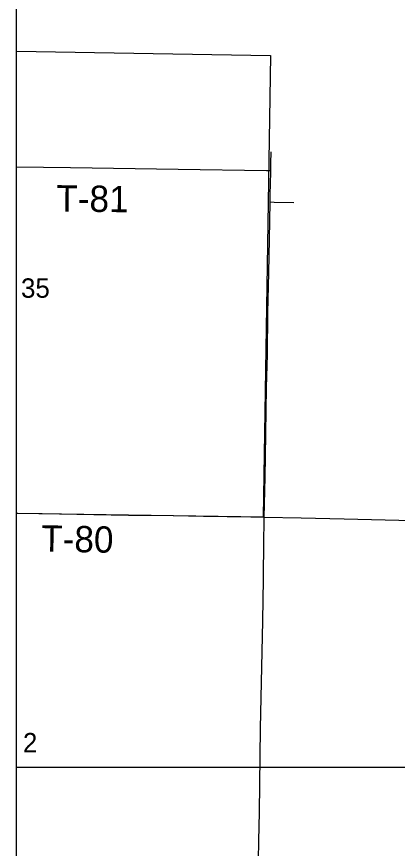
# Model space of a CAD drawing. Extents: x 0 to 68, y 0 to 52.9.
# Drawn here: x 49.517 to 51.689, y 42.989 to 47.729 of the extents above; entities that cross this region are included whole.
import ezdxf

# ---------------------------------------------------------------- set-up
doc = ezdxf.new("R2010")
doc.units = 0
for name, color, linetype in [('Default', 7, 'Continuous'), ('GM_X_Township_Road', 7, 'Continuous'), ('GM_X_Township_Road_Text', 7, 'Continuous')]:
    doc.layers.add(name, color=color, linetype=linetype)

msp = doc.modelspace()

# ---------------------------------------------------------------- linework, layer by layer
at = {"layer": 'Default'}
for p, q in [((49.5172, 34.4614), (49.5172, 52.9414)), ((49.5172, 43.4514), (67.9972, 43.4514))]:
    msp.add_line(p, q, dxfattribs=at)
msp.add_lwpolyline([(49.5172, 47.5317), (50.965, 47.5066), (50.9246, 44.8761), (49.5172, 44.8972)], dxfattribs=at)
at = {"layer": 'GM_X_Township_Road'}
for points in [[(50.9676, 46.8517), (50.9679, 46.8919), (50.9692, 46.959)], [(49.5172, 46.8723), (49.8238, 46.8682), (50.4384, 46.8586), (50.9432, 46.8521), (50.9676, 46.8517)], [(50.963, 46.6725), (50.9637, 46.7138), (50.9676, 46.8429), (50.9676, 46.8517)], [(50.9298, 44.8767), (50.9316, 44.9512), (50.9346, 45.1069), (50.9365, 45.2217), (50.9413, 45.4841), (50.943, 45.6153), (50.9478, 45.8036), (50.9511, 46.0415), (50.9553, 46.271), (50.9594, 46.4596), (50.963, 46.6725)], [(50.963, 46.6725), (50.9863, 46.672), (51.0979, 46.6695)], [(49.5172, 44.8991), (49.5245, 44.899), (49.6638, 44.8963), (50.156, 44.8878), (50.4103, 44.8855), (50.5824, 44.882), (50.8532, 44.8783), (50.9298, 44.8767)], [(50.887, 42.337), (50.8906, 42.5401), (50.8957, 42.8107), (50.8992, 43.0321), (50.9026, 43.196), (50.9087, 43.6712), (50.9212, 44.2861), (50.9251, 44.5239), (50.9275, 44.7453), (50.9293, 44.8435), (50.9298, 44.8767)], [(50.9298, 44.8767), (51.1402, 44.8725), (51.3862, 44.8673), (51.6978, 44.8598), (52.1325, 44.8509), (52.2551, 44.8479)]]:
    msp.add_lwpolyline(points, dxfattribs=at)

# ---------------------------------------------------------------- texts
at = {"layer": 'Default'}
for s, p in [('35', (49.5422, 46.1267)), ('2', (49.5532, 43.536))]:
    msp.add_text(s, height=0.1105, rotation=0, dxfattribs=at).set_placement(p)
at = {"layer": 'GM_X_Township_Road_Text'}
for s, rotation, p in [('T-81', 359.2931, (49.7428, 46.6187)), ('T-80', 358.9386, (49.6562, 44.6806))]:
    msp.add_text(s, height=0.15, rotation=rotation, dxfattribs=at).set_placement(p)

doc.saveas('drawing.dxf')
